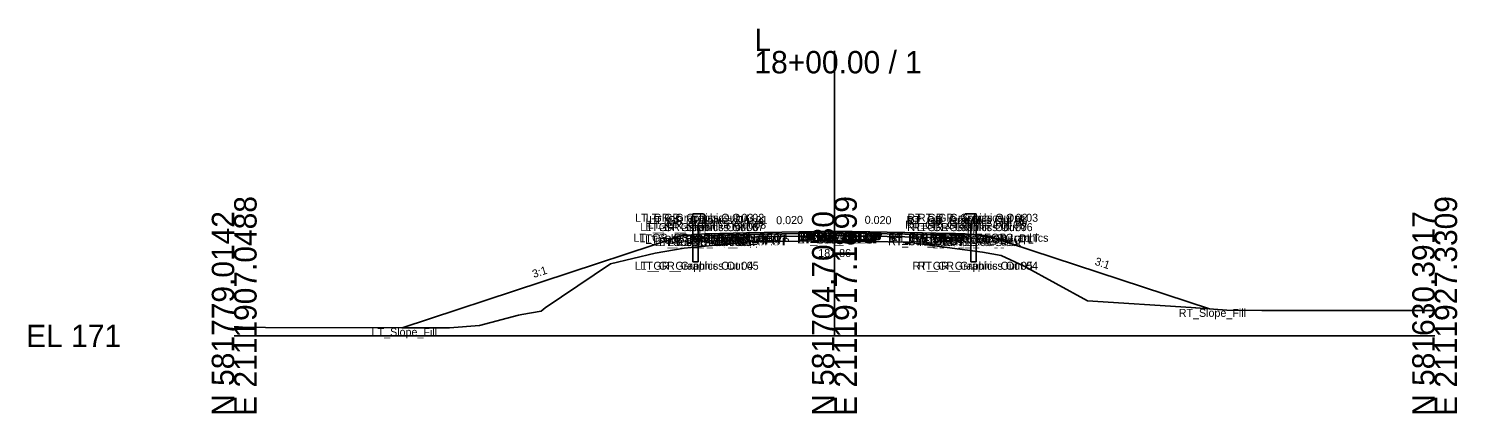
# Model space of a CAD drawing. Extents: x -486 to 1153, y -333 to 9539.
# Drawn here: x -25.7 to 152.8, y 8490.3 to 8538.4 of the extents above; entities that cross this region are included whole.
import ezdxf

# ---------------------------------------------------------------- set-up
doc = ezdxf.new("R2010")
doc.units = 0
for name, color, linetype in [('Default', 7, 'Continuous'), ('Exist Cross Section Cell', 7, 'Continuous'), ('Exist XS Ground Line', 7, 'Continuous'), ('Prop CMT Guardrail Graphics', 7, 'Continuous'), ('Prop CMT Pvmt Course 1', 7, 'Continuous'), ('Prop CMT Pvmt Course 2', 7, 'Continuous'), ('Prop CMT Pvmt Course 3', 7, 'Continuous'), ('Prop CMT Pvmt Surface', 7, 'Continuous'), ('Prop CMT Pvmt Surface Shoulder', 7, 'Continuous'), ('Prop CMT Shld Paved Course 1', 7, 'Continuous'), ('Prop CMT Shld Paved Course 2', 7, 'Continuous'), ('Prop CMT Shld Paved Course 3', 7, 'Continuous'), ('Prop CMT Slope Grass', 7, 'Continuous'), ('Prop CMT Subgrade Earthwork', 7, 'Continuous'), ('Prop XS Earthwork Shape', 7, 'Continuous'), ('Prop XS SE Text', 7, 'Continuous'), ('Prop XS Side Slope Text', 7, 'Continuous'), ('Scratch_Level_0', 7, 'Continuous')]:
    doc.layers.add(name, color=color, linetype=linetype)

msp = doc.modelspace()

# ---------------------------------------------------------------- linework, layer by layer
at = {"layer": 'Exist Cross Section Cell'}
for p, q in [((75, 8500), (75, 8535.62)), ((0, 8500), (75, 8500)), ((75, 8500), (150, 8500))]:
    msp.add_line(p, q, dxfattribs=at)
at = {"layer": 'Exist XS Ground Line'}
for p, q in [((52.59, 8510.33), (56.21, 8510.96)), ((56.21, 8510.96), (64.98, 8511.79)), ((64.98, 8511.79), (67, 8511.81)), ((67, 8511.81), (74.33, 8511.87)), ((74.33, 8511.87), (75, 8511.86)), ((75, 8511.86), (76.6, 8511.83)), ((76.6, 8511.83), (84.25, 8511.73)), ((84.25, 8511.73), (86.88, 8511.35)), ((86.88, 8511.35), (93.49, 8510.45)), ((38.85, 8503.49), (47, 8509.02)), ((47, 8509.02), (52.59, 8510.33)), ((93.49, 8510.45), (95.84, 8510.05)), ((95.84, 8510.05), (98.71, 8508.7)), ((98.71, 8508.7), (106.61, 8504.4)), ((106.61, 8504.4), (119.57, 8503.55)), ((119.57, 8503.55), (124.01, 8503.21)), ((30.64, 8501.31), (35.53, 8502.61)), ((35.53, 8502.61), (35.93, 8502.66)), ((35.93, 8502.66), (38.34, 8503.1)), ((38.34, 8503.1), (38.85, 8503.49)), ((124.01, 8503.21), (128.41, 8503.19)), ((128.41, 8503.19), (150, 8503.16)), ((0, 8501.13), (0.54, 8501.13)), ((0.54, 8501.13), (1.55, 8501.06)), ((1.55, 8501.06), (2.55, 8501.08)), ((2.55, 8501.08), (3.92, 8501.05)), ((3.92, 8501.05), (26.89, 8500.99)), ((26.89, 8500.99), (30.64, 8501.31))]:
    msp.add_line(p, q, dxfattribs=at)
at = {"layer": 'Prop CMT Guardrail Graphics'}
for points in [[(57.3, 8509.27), (57.3, 8515.27)], [(57.3, 8515.27), (58.63, 8515.27), (58.9, 8514.98)], [(58.9, 8514.4), (58.63, 8514.1), (57.96, 8514.1)], [(58.9, 8514.98), (58.63, 8514.69)], [(58.63, 8514.69), (58.9, 8514.4)], [(92.7, 8515.27), (91.37, 8515.27), (91.1, 8514.98)], [(91.1, 8514.98), (91.37, 8514.69)], [(91.37, 8514.69), (91.1, 8514.4)], [(91.1, 8514.4), (91.37, 8514.1), (92.04, 8514.1)], [(92.7, 8509.27), (92.7, 8515.27)], [(57.96, 8514.1), (57.96, 8509.27)], [(92.04, 8514.1), (92.04, 8509.27)], [(57.96, 8509.27), (57.3, 8509.27)], [(92.04, 8509.27), (92.7, 8509.27)]]:
    msp.add_lwpolyline(points, dxfattribs=at)
at = {"layer": 'Prop CMT Pvmt Course 1'}
for points in [[(75, 8513.1), (64, 8512.88)], [(64, 8512.67), (75, 8512.89)], [(64, 8512.88), (64, 8512.67)], [(75, 8512.89), (75, 8513.1)], [(75, 8513.1), (86, 8512.88)], [(75, 8512.89), (75, 8513.1)], [(86, 8512.67), (75, 8512.89)], [(86, 8512.88), (86, 8512.67)]]:
    msp.add_lwpolyline(points, dxfattribs=at)
msp.add_lwpolyline([(75, 8512.89), (75, 8512.97), (75, 8512.97), (75, 8512.89)], close=True, dxfattribs=at)
msp.add_lwpolyline([(75, 8512.89), (75, 8512.97), (75, 8512.97), (75, 8512.89)], close=True, dxfattribs=at)
at = {"layer": 'Prop CMT Pvmt Course 2'}
for points in [[(75, 8512.89), (64, 8512.67)], [(64, 8512.67), (64, 8512.34)], [(64, 8512.34), (75, 8512.56)], [(75, 8512.56), (75, 8512.89)], [(75, 8512.56), (75, 8512.89)], [(75, 8512.89), (86, 8512.67)], [(86, 8512.34), (75, 8512.56)], [(86, 8512.67), (86, 8512.34)]]:
    msp.add_lwpolyline(points, dxfattribs=at)
at = {"layer": 'Prop CMT Pvmt Course 3'}
for points in [[(75, 8512.56), (64, 8512.34)], [(75, 8512.56), (75, 8512.56)], [(75, 8512.56), (86, 8512.34)], [(75, 8512.56), (75, 8512.56)], [(64, 8512.34), (64, 8512.34)], [(86, 8512.34), (86, 8512.34)]]:
    msp.add_lwpolyline(points, dxfattribs=at)
at = {"layer": 'Prop CMT Pvmt Surface'}
for points in [[(75, 8513.1), (64, 8512.88)], [(75, 8513.1), (86, 8512.88)]]:
    msp.add_lwpolyline(points, dxfattribs=at)
at = {"layer": 'Prop CMT Pvmt Surface Shoulder'}
for points in [[(64, 8512.88), (59, 8512.78)], [(86, 8512.88), (91, 8512.78)]]:
    msp.add_lwpolyline(points, dxfattribs=at)
at = {"layer": 'Prop CMT Shld Paved Course 1'}
for points in [[(64, 8512.88), (59, 8512.78), (58.79, 8512.57)], [(58.79, 8512.57), (64, 8512.67)], [(64, 8512.67), (64, 8512.88)], [(86, 8512.88), (91, 8512.78), (91.21, 8512.57)], [(86, 8512.67), (86, 8512.88)], [(91.21, 8512.57), (86, 8512.67)]]:
    msp.add_lwpolyline(points, dxfattribs=at)
at = {"layer": 'Prop CMT Shld Paved Course 2'}
for points in [[(64, 8512.67), (58.79, 8512.57), (58.45, 8512.23)], [(64, 8512.34), (64, 8512.67)], [(86, 8512.67), (91.21, 8512.57), (91.55, 8512.23)], [(86, 8512.34), (86, 8512.67)], [(58.45, 8512.23), (64, 8512.34)], [(91.55, 8512.23), (86, 8512.34)]]:
    msp.add_lwpolyline(points, dxfattribs=at)
at = {"layer": 'Prop CMT Shld Paved Course 3'}
for points in [[(64, 8512.34), (58.45, 8512.23)], [(58.45, 8512.23), (58.45, 8512.23), (58.45, 8512.23)], [(64, 8512.34), (64, 8512.34)], [(86, 8512.34), (91.55, 8512.23)], [(86, 8512.34), (86, 8512.34)], [(91.55, 8512.23), (91.55, 8512.23), (91.55, 8512.23)]]:
    msp.add_lwpolyline(points, dxfattribs=at)
at = {"layer": 'Prop CMT Slope Grass'}
for points in [[(55.9, 8512.53), (20.97, 8501)], [(58.9, 8512.77), (55.9, 8512.53)], [(59, 8512.78), (58.9, 8512.77)], [(91, 8512.78), (91.1, 8512.77)], [(91.1, 8512.77), (94.1, 8512.53)], [(94.1, 8512.53), (121.85, 8503.38)]]:
    msp.add_lwpolyline(points, dxfattribs=at)
at = {"layer": 'Prop CMT Subgrade Earthwork'}
for points in [[(58.45, 8512.23), (57.98, 8512.7)], [(75, 8512.56), (64, 8512.34)], [(75, 8512.56), (86, 8512.34)], [(91.55, 8512.23), (92.02, 8512.7)], [(64, 8512.34), (58.45, 8512.23)], [(86, 8512.34), (91.55, 8512.23)]]:
    msp.add_lwpolyline(points, dxfattribs=at)
at = {"layer": 'Prop XS Earthwork Shape'}
msp.add_lwpolyline([(30.64, 8501.31), (35.53, 8502.61), (35.93, 8502.66), (38.34, 8503.1), (38.85, 8503.49), (47, 8509.02), (52.59, 8510.33), (56.21, 8510.96), (64.98, 8511.79), (67, 8511.81), (74.33, 8511.87), (75, 8511.86), (76.6, 8511.83), (84.25, 8511.73), (86.88, 8511.35), (93.49, 8510.45), (95.84, 8510.05), (98.71, 8508.7), (106.61, 8504.4), (119.57, 8503.55), (121.85, 8503.38), (94.1, 8512.53), (92.02, 8512.7), (91.55, 8512.23), (86, 8512.34), (75, 8512.56), (64, 8512.34), (58.45, 8512.23), (57.98, 8512.7), (55.9, 8512.53), (20.97, 8501), (26.89, 8500.99)], close=True, dxfattribs=at)

# ---------------------------------------------------------------- texts
at = {"layer": 'Default'}
for s, height, p in [('182.86', 1, (72.98, 8509.86)), ('-', 0.0001, (0, 8500))]:
    msp.add_text(s, height=height, dxfattribs=at).set_placement(p)
at = {"layer": 'Exist Cross Section Cell'}
for s, p in [('L', (65, 8535.62)), ('18+00.00 / 1', (65, 8532.82)), ('EL 171', (-26, 8498.6))]:
    msp.add_text(s, height=2.8, dxfattribs=at).set_placement(p)
for s, p in [('E 2111907.0488', (2.8, 8490)), ('E 2111917.1899', (77.8, 8490)), ('E 2111927.3309', (152.8, 8490)), ('N 581779.0142', (0, 8490)), ('N 581704.7030', (75, 8490)), ('N 581630.3917', (150, 8490))]:
    msp.add_text(s, height=2.8, rotation=90, dxfattribs=at).set_placement(p)
at = {"layer": 'Prop XS SE Text'}
for rotation, p in [(1.1458, (67.73, 8513.95)), (358.8542, (78.77, 8514.02))]:
    msp.add_text('0.020', height=1, rotation=rotation, dxfattribs=at).set_placement(p)
at = {"layer": 'Prop XS Side Slope Text'}
for rotation, p in [(341.7371, (107.45, 8508.91)), (18.2629, (37.43, 8507.23))]:
    msp.add_text('3:1', height=1, rotation=rotation, dxfattribs=at).set_placement(p)
at = {"layer": 'Scratch_Level_0'}
for s, p in [('LT_GR_Graphics Out 03', (50.08, 8514.27)), ('LT_GR_Graphics Out 09', (51.4, 8513.69)), ('LT_GR_Graphics Out 02', (51.43, 8514.27)), ('LT_GR_Graphics Out 08', (51.67, 8513.4)), ('LT_GR_Graphics Out 01', (51.85, 8513.98)), ('RT_GR_Graphics Out 08', (83.81, 8513.4)), ('RT_GR_Graphics Out 01', (83.99, 8513.98)), ('RT_GR_Graphics Out 09', (84.09, 8513.69)), ('RT_GR_Graphics Out 02', (84.11, 8514.27)), ('RT_GR_Graphics Out 03', (85.43, 8514.27)), ('LT_GS_OS_GR_Face_Graphics', (49.9, 8511.77)), ('LT_Sub_Trench_Out_DLT', (50.63, 8511.7)), ('LT_GR_Graphics Out 06', (50.74, 8513.1)), ('LT_GS_OS_CTL', (51.36, 8511.53)), ('LT_GR_Graphics Out 07', (51.39, 8513.1)), ('LT_PS2_OEOP', (54.57, 8511.57)), ('LT_PS1_OEOP', (54.91, 8511.78)), ('LT_PV2_OEOT', (59.75, 8511.67)), ('LT_PV1_OEOT', (59.87, 8511.88)), ('RT_PV2_OEEOP', (70.33, 8511.89)), ('RT_PV3_OEEOP', (70.33, 8511.56)), ('RT_Sub_OEEOP', (70.36, 8511.56)), ('LT_PV2_OEEOP', (70.39, 8511.89)), ('LT_PV3_OEEOP', (70.39, 8511.56)), ('LT_Sub_OEEOP', (70.42, 8511.56)), ('RT_PV1_OEEOP', (70.45, 8511.97)), ('LT_PV1_OEEOP', (70.51, 8511.97)), ('RT_PV2_IEEOP', (70.71, 8511.89)), ('LT_PV2_IEEOP', (70.77, 8511.89)), ('RT_PV1_IEEOP', (70.83, 8511.97)), ('LT_PV1_IEEOP', (70.89, 8511.97)), ('PV2_PGL', (72.35, 8511.89)), ('PV1_PGL', (72.47, 8512.1)), ('RT_PV2_OEOT', (81.69, 8511.67)), ('RT_PV1_OEOT', (81.81, 8511.88)), ('RT_GS_OS_GR_Face_Graphics', (82.04, 8511.77)), ('RT_GR_Graphics Out 07', (84.07, 8513.1)), ('RT_Sub_Trench_Out_DLT', (84.61, 8511.7)), ('RT_GR_Graphics Out 06', (84.75, 8513.1)), ('RT_PS1_OEOP', (86.85, 8511.78)), ('RT_PS2_OEOP', (86.94, 8511.57)), ('RT_GS_OS_CTL', (89.5, 8511.53)), ('LT_Sub_Trench_Out', (52.56, 8511.23)), ('LT_PS3_Shelf_Out', (53.1, 8511.23)), ('LT_PS3_OEOP', (54.23, 8511.23)), ('LT_PV3_OEOT', (59.75, 8511.34)), ('LT_Sub_OEOT', (59.77, 8511.34)), ('RT_PV3_OEOT', (81.69, 8511.34)), ('RT_Sub_OEOT', (81.71, 8511.34)), ('RT_Sub_Trench_Out', (85.6, 8511.23)), ('RT_PS3_Shelf_Out', (86.15, 8511.23)), ('RT_PS3_OEOP', (87.28, 8511.23)), ('LT_GR_Graphics Out 04', (50.07, 8508.27)), ('LT_GR_Graphics Out 05', (50.74, 8508.27)), ('RT_GR_Graphics Out 05', (84.76, 8508.27)), ('RT_GR_Graphics Out 04', (85.41, 8508.27)), ('RT_Slope_Fill', (118.02, 8502.38)), ('LT_Slope_Fill', (17.17, 8499.99))]:
    msp.add_text(s, height=1, dxfattribs=at).set_placement(p)

doc.saveas('drawing.dxf')
